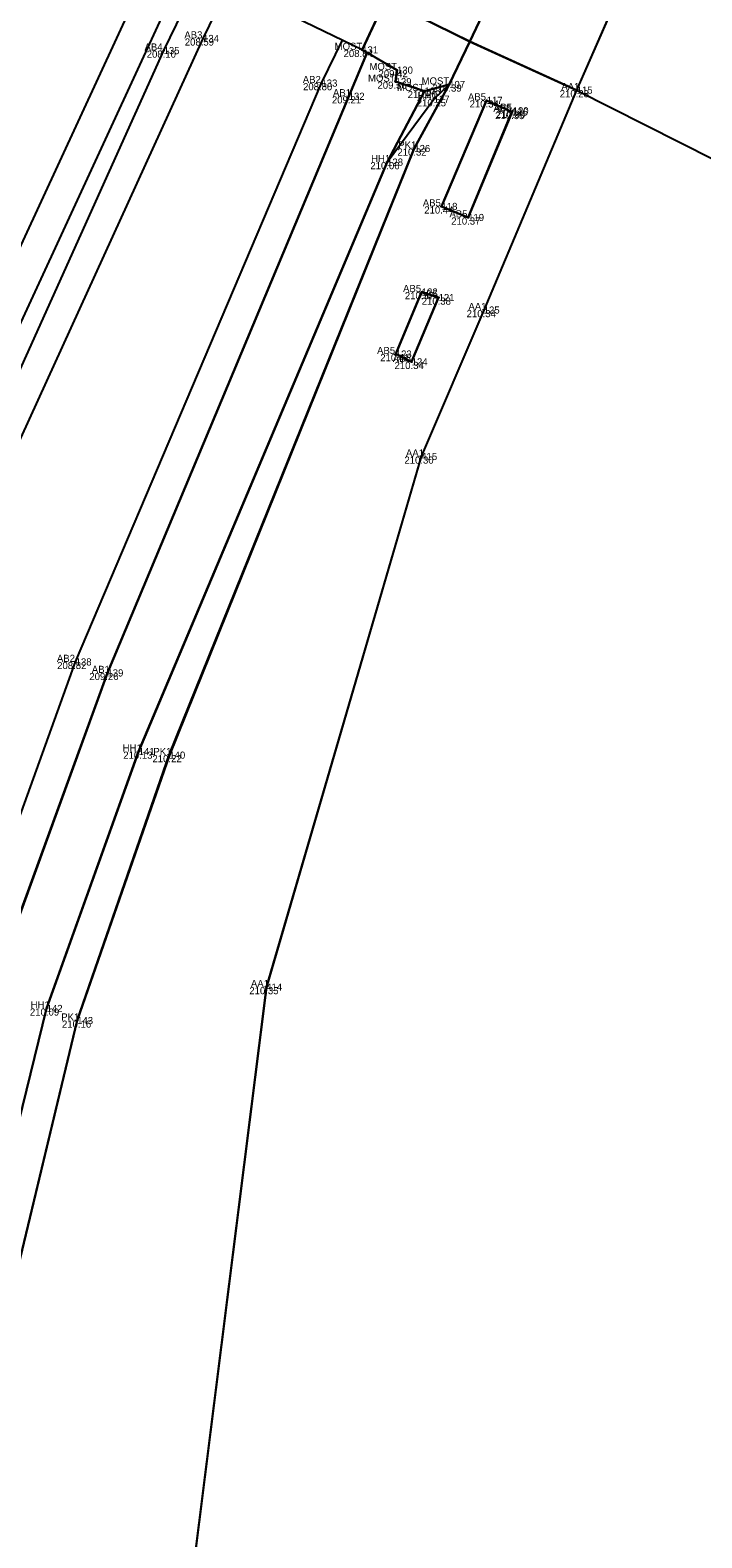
# Model space of a CAD drawing. Extents: x -263091 to -262565, y -1238731 to -1237092.
# Drawn here: x -262793.24 to -262774.42, y -1237721.96 to -1237679.73 of the extents above; entities that cross this region are included whole.
import ezdxf

# ---------------------------------------------------------------- set-up
doc = ezdxf.new("R2010")
doc.units = 0
for name, color, linetype in [('01_Hrana_betónu', 7, 'Continuous'), ('02_Oplotenie', 7, 'Continuous'), ('03_Asfalt', 7, 'Continuous'), ('04_Most', 7, 'Continuous'), ('05_Hrana_terénu', 7, 'Continuous'), ('08_Mimo_zelene', 7, 'Continuous'), ('10', 7, 'Continuous'), ('Groma (21)', 7, 'Continuous'), ('Groma (22)', 7, 'Continuous'), ('Groma (23)', 7, 'Continuous'), ('Groma (24)', 7, 'Continuous'), ('U004_Betónové_panely', 7, 'Continuous'), ('U004_Ostatné_plochy', 7, 'Continuous'), ('U004_Zeleň_mimo', 7, 'Continuous'), ('U004_Zeleň_vnútro', 7, 'Continuous'), ('U004_Zeleň_zatrávňovač', 7, 'Continuous'), ('U005_Ostatné_plochy', 7, 'Continuous'), ('U005_Zeleň_mimo', 7, 'Continuous')]:
    doc.layers.add(name, color=color, linetype=linetype)

msp = doc.modelspace()

# ---------------------------------------------------------------- linework, layer by layer
at = {"layer": '01_Hrana_betónu'}
msp.add_line((-262783.935, -1237680.285), (-262783.282, -1237678.876), dxfattribs=at)
for points in [[(-262828.366, -1237932.946), (-262828.106, -1237929.217), (-262827.649, -1237919.578), (-262827.369, -1237915.073), (-262826.968, -1237906.664), (-262825.835, -1237884.909), (-262824.318, -1237870.338), (-262822.252, -1237856.88), (-262820.394, -1237847.242), (-262816.344, -1237828.005), (-262811.527, -1237806.128), (-262807.485, -1237786.652), (-262805.817, -1237767.526), (-262804.904, -1237743.876), (-262804.544, -1237721.54), (-262802.773, -1237710.111), (-262800.948, -1237703.699), (-262796.578, -1237692.416), (-262790.297, -1237678.834), (-262789.671, -1237677.512)], [(-262788.862, -1237677.903), (-262789.612, -1237679.5), (-262795.758, -1237692.783), (-262800.102, -1237704.105), (-262801.904, -1237710.319), (-262803.638, -1237721.631), (-262804.041, -1237743.855), (-262804.886, -1237767.666), (-262806.567, -1237786.84), (-262810.653, -1237806.707), (-262815.575, -1237828.361), (-262819.614, -1237847.41), (-262821.404, -1237856.927), (-262823.638, -1237870.532), (-262825.083, -1237884.947), (-262826.299, -1237906.725), (-262827.242, -1237929.453), (-262827.527, -1237933.008)], [(-262788.441, -1237678.106), (-262789.499, -1237680.304), (-262796.488, -1237695.789), (-262799.561, -1237704.378), (-262801.599, -1237711.648), (-262803.17, -1237722.277), (-262803.523, -1237744.912), (-262804.331, -1237767.555), (-262806.033, -1237786.907), (-262810.428, -1237808.027), (-262815.321, -1237829.941), (-262818.5, -1237845.545), (-262820.865, -1237857.635), (-262822.962, -1237871.266), (-262824.386, -1237885.795), (-262825.49, -1237906.658), (-262826.835, -1237930.337), (-262826.931, -1237933.053)], [(-262825.987, -1237933.123), (-262825.899, -1237930.36), (-262825.137, -1237919.703), (-262824.89, -1237915.193), (-262824.65, -1237906.715), (-262823.596, -1237885.855), (-262822.137, -1237871.403), (-262820.061, -1237857.781), (-262817.692, -1237845.812), (-262814.459, -1237830.149), (-262809.645, -1237808.205), (-262805.191, -1237787.117), (-262803.484, -1237767.641), (-262802.568, -1237744.998), (-262802.266, -1237722.317), (-262800.862, -1237712.121), (-262798.805, -1237704.616), (-262795.791, -1237696.17), (-262788.393, -1237679.964), (-262787.674, -1237678.477)], [(-262785.076, -1237681.215), (-262784.491, -1237680.016)], [(-262783.803, -1237680.361), (-262791.072, -1237697.733), (-262794.156, -1237706.196), (-262796.111, -1237713.494), (-262797.353, -1237722.795), (-262798.006, -1237745.028), (-262798.995, -1237767.834), (-262800.837, -1237788.066), (-262805.174, -1237808.895), (-262810.048, -1237831.05), (-262813.207, -1237846.368), (-262815.438, -1237858.025), (-262817.519, -1237871.503), (-262819.01, -1237885.889), (-262819.761, -1237906.843), (-262819.991, -1237915.564)], [(-262820.488, -1237916.085), (-262820.893, -1237915.574), (-262820.599, -1237906.725), (-262819.894, -1237885.916), (-262818.364, -1237871.361), (-262816.365, -1237858.042), (-262814.122, -1237846.343), (-262810.891, -1237830.85), (-262806.137, -1237808.69), (-262801.736, -1237787.923), (-262799.952, -1237767.772), (-262798.979, -1237744.912), (-262798.159, -1237722.635), (-262796.927, -1237713.21), (-262795.035, -1237705.927), (-262791.963, -1237697.425), (-262785.076, -1237681.215)]]:
    msp.add_lwpolyline(points, dxfattribs=at)
at = {"layer": '02_Oplotenie'}
msp.add_lwpolyline([(-262782.476, -1237683.046), (-262789.338, -1237700.035), (-262791.92, -1237707.468), (-262793.68, -1237714.792), (-262794.853, -1237723.195), (-262795.698, -1237745.299), (-262796.564, -1237768.081), (-262798.719, -1237788.188), (-262802.852, -1237809.448), (-262807.527, -1237831.589), (-262810.764, -1237846.834), (-262812.842, -1237857.763), (-262814.888, -1237871.127), (-262816.319, -1237886.182), (-262816.945, -1237895.233), (-262817.687, -1237906.993), (-262818.366, -1237915.571), (-262818.764, -1237925.136)], dxfattribs=at)
at = {"layer": '03_Asfalt'}
for points in [[(-262724.746, -1237307.401), (-262727.828, -1237308.991), (-262728.093, -1237318.612), (-262728.491, -1237332.383), (-262729.117, -1237356.253), (-262729.803, -1237378.892), (-262730.272, -1237401.612), (-262730.633, -1237425.617), (-262730.625, -1237458.196), (-262731.018, -1237478.61), (-262730.917, -1237502.542), (-262731.001, -1237524.284), (-262731.468, -1237547.904), (-262731.892, -1237556.788), (-262732.535, -1237567.203), (-262733.679, -1237576.214), (-262736.504, -1237586.306), (-262740.104, -1237594.868), (-262744.783, -1237605.686), (-262753.189, -1237625.134), (-262761.527, -1237644.232), (-262769.984, -1237663.306), (-262774.379, -1237673.302), (-262777.928, -1237681.411)], [(-262777.928, -1237681.411), (-262780.531, -1237687.57), (-262782.281, -1237691.672), (-262786.624, -1237706.531), (-262791.645, -1237746.487), (-262793.969, -1237766.446), (-262796.149, -1237782.824), (-262801.035, -1237810.714), (-262803.747, -1237825.804), (-262807.32, -1237845.566), (-262809.566, -1237858.112), (-262812.403, -1237873.547), (-262813.944, -1237886.41), (-262814.5, -1237895.481), (-262816.945, -1237895.233)]]:
    msp.add_lwpolyline(points, dxfattribs=at)
at = {"layer": '04_Most'}
for points in [[(-262794.832, -1237673.105), (-262794.423, -1237672.239), (-262794.016, -1237671.765), (-262792.919, -1237672.236), (-262791.945, -1237673.175), (-262782.754, -1237677.736), (-262781.704, -1237678.283), (-262781.563, -1237678.037), (-262780.7, -1237678.426), (-262780.481, -1237679.127), (-262780.925, -1237680.054)], [(-262780.925, -1237680.054), (-262781.499, -1237681.254), (-262782.189, -1237681.436), (-262783, -1237681.174), (-262782.961, -1237680.851), (-262783.935, -1237680.285), (-262793.299, -1237675.758), (-262794.227, -1237675.288), (-262794.619, -1237675.515), (-262795.493, -1237674.504), (-262794.832, -1237673.105)]]:
    msp.add_lwpolyline(points, dxfattribs=at)
at = {"layer": '05_Hrana_terénu'}
msp.add_lwpolyline([(-262819.123, -1237925.833), (-262819.193, -1237924.361), (-262818.874, -1237915.472), (-262818.289, -1237906.84), (-262817.033, -1237886.241), (-262815.506, -1237871.209), (-262813.693, -1237857.604), (-262811.493, -1237846.649), (-262808.389, -1237831.401), (-262803.328, -1237809.401), (-262799.108, -1237788.219), (-262797.264, -1237767.972), (-262796.32, -1237745.233), (-262795.609, -1237723.113), (-262794.587, -1237714.488), (-262792.775, -1237707.13), (-262790.198, -1237699.936), (-262783.238, -1237683.427), (-262781.933, -1237681.667), (-262781.499, -1237681.254)], dxfattribs=at)
at = {"layer": '08_Mimo_zelene'}
for points in [[(-262781.713, -1237684.669), (-262780.448, -1237681.698), (-262779.738, -1237682.023), (-262780.967, -1237684.978)], [(-262782.55, -1237689.021), (-262782.994, -1237688.803), (-262782.266, -1237687.066), (-262781.795, -1237687.221)]]:
    msp.add_lwpolyline(points, close=True, dxfattribs=at)
at = {"layer": '10'}
msp.add_lwpolyline([(-262813.033, -1237664.011), (-262780.925, -1237680.054), (-262777.93, -1237681.41), (-262750.961, -1237695.025)], dxfattribs=at)
at = {"layer": 'Groma (21)'}
for centre in [(-262788.393, -1237679.964), (-262783.935, -1237680.285), (-262789.499, -1237680.304), (-262782.961, -1237680.851), (-262785.076, -1237681.215), (-262783, -1237681.174), (-262782.189, -1237681.436), (-262781.499, -1237681.254), (-262777.928, -1237681.412), (-262784.315, -1237681.584), (-262781.933, -1237681.667), (-262780.448, -1237681.698), (-262779.738, -1237682.023), (-262779.72, -1237681.99), (-262782.476, -1237683.046), (-262783.238, -1237683.427), (-262781.713, -1237684.669), (-262780.967, -1237684.978), (-262782.266, -1237687.066), (-262781.795, -1237687.221), (-262780.531, -1237687.57), (-262782.994, -1237688.803), (-262782.55, -1237689.021), (-262782.281, -1237691.672), (-262791.963, -1237697.425), (-262791.072, -1237697.733), (-262790.198, -1237699.936), (-262789.338, -1237700.035), (-262786.624, -1237706.531), (-262792.775, -1237707.13), (-262791.92, -1237707.468)]:
    msp.add_circle(centre, 0.01, dxfattribs=at)
at = {"layer": 'U004_Betónové_panely'}
msp.add_lwpolyline([(-262809.47, -1237744.21), (-262809.35, -1237719.32), (-262807.76, -1237709.13), (-262805.58, -1237701.26), (-262801.1, -1237689.83), (-262795.06, -1237676.27), (-262794.18, -1237676.61), (-262793.3, -1237675.76), (-262792.52, -1237674.26), (-262788.97, -1237676.03), (-262788.17, -1237676.43), (-262787.74, -1237676.65), (-262786.97, -1237677.03), (-262783.28, -1237678.88), (-262783.94, -1237680.28), (-262783.8, -1237680.36), (-262791.07, -1237697.73), (-262794.16, -1237706.2), (-262796.11, -1237713.49), (-262797.35, -1237722.8)], dxfattribs=at)
msp.add_lwpolyline([(-262809.47, -1237744.21), (-262809.35, -1237719.32), (-262807.76, -1237709.13), (-262805.58, -1237701.26), (-262801.1, -1237689.83), (-262795.06, -1237676.27), (-262794.18, -1237676.61), (-262793.3, -1237675.76), (-262792.52, -1237674.26), (-262788.97, -1237676.03), (-262788.17, -1237676.43), (-262787.74, -1237676.65), (-262786.97, -1237677.03), (-262783.28, -1237678.88), (-262783.94, -1237680.28), (-262783.8, -1237680.36), (-262791.07, -1237697.73), (-262794.16, -1237706.2), (-262796.11, -1237713.49), (-262797.35, -1237722.8)], dxfattribs=at)
at = {"layer": 'U004_Ostatné_plochy'}
for points in [[(-262783.94, -1237680.28), (-262783.28, -1237678.88), (-262780.92, -1237680.05), (-262781.5, -1237681.25), (-262782.19, -1237681.44), (-262783, -1237681.17), (-262782.96, -1237680.85)], [(-262781.71, -1237684.67), (-262780.45, -1237681.7), (-262779.74, -1237682.02), (-262780.97, -1237684.98)], [(-262781.8, -1237687.22), (-262782.55, -1237689.02), (-262782.99, -1237688.8), (-262782.27, -1237687.07)]]:
    msp.add_lwpolyline(points, close=True, dxfattribs=at)
msp.add_lwpolyline([(-262782.19, -1237681.44), (-262783, -1237681.17), (-262782.96, -1237680.85), (-262783.94, -1237680.28), (-262783.28, -1237678.88), (-262780.92, -1237680.05), (-262781.5, -1237681.25), (-262782.19, -1237681.44)], dxfattribs=at)
at = {"layer": 'U004_Zeleň_mimo'}
msp.add_lwpolyline([(-262794.85, -1237723.2), (-262793.68, -1237714.79), (-262791.92, -1237707.47), (-262789.34, -1237700.03), (-262782.48, -1237683.05), (-262781.5, -1237681.25), (-262780.92, -1237680.05), (-262777.93, -1237681.41), (-262780.53, -1237687.57), (-262782.28, -1237691.67), (-262786.62, -1237706.53), (-262791.65, -1237746.49)], dxfattribs=at)
for points in [[(-262780.97, -1237684.98), (-262779.74, -1237682.02), (-262780.45, -1237681.7), (-262781.71, -1237684.67)], [(-262781.8, -1237687.22), (-262782.27, -1237687.07), (-262782.99, -1237688.8), (-262782.55, -1237689.02)]]:
    msp.add_lwpolyline(points, close=True, dxfattribs=at)
at = {"layer": 'U004_Zeleň_vnútro'}
msp.add_lwpolyline([(-262795.61, -1237723.11), (-262794.59, -1237714.49), (-262792.78, -1237707.13), (-262790.2, -1237699.94), (-262783.24, -1237683.43), (-262782.19, -1237681.44), (-262781.5, -1237681.25), (-262782.48, -1237683.05), (-262789.34, -1237700.03), (-262791.92, -1237707.47), (-262793.68, -1237714.79), (-262794.85, -1237723.2)], dxfattribs=at)
msp.add_lwpolyline([(-262795.61, -1237723.11), (-262794.59, -1237714.49), (-262792.78, -1237707.13), (-262790.2, -1237699.94), (-262783.24, -1237683.43), (-262782.19, -1237681.44), (-262781.5, -1237681.25), (-262782.48, -1237683.05), (-262789.34, -1237700.03), (-262791.92, -1237707.47), (-262793.68, -1237714.79), (-262794.85, -1237723.2)], dxfattribs=at)
at = {"layer": 'U004_Zeleň_zatrávňovač'}
msp.add_lwpolyline([(-262797.35, -1237722.8), (-262796.11, -1237713.49), (-262794.16, -1237706.2), (-262791.07, -1237697.73), (-262783.8, -1237680.36), (-262782.96, -1237680.85), (-262783, -1237681.17), (-262782.19, -1237681.44), (-262783.24, -1237683.43), (-262790.2, -1237699.94), (-262792.78, -1237707.13), (-262794.59, -1237714.49), (-262795.61, -1237723.11)], dxfattribs=at)
msp.add_lwpolyline([(-262797.35, -1237722.8), (-262796.11, -1237713.49), (-262794.16, -1237706.2), (-262791.07, -1237697.73), (-262783.8, -1237680.36), (-262782.96, -1237680.85), (-262783, -1237681.17), (-262782.19, -1237681.44), (-262783.24, -1237683.43), (-262790.2, -1237699.94), (-262792.78, -1237707.13), (-262794.59, -1237714.49), (-262795.61, -1237723.11)], dxfattribs=at)
at = {"layer": 'U005_Ostatné_plochy'}
msp.add_lwpolyline([(-262783.28, -1237678.88), (-262782.75, -1237677.74), (-262781.56, -1237678.04), (-262780.7, -1237678.43), (-262780.48, -1237679.13), (-262780.92, -1237680.05)], close=True, dxfattribs=at)
msp.add_lwpolyline([(-262780.92, -1237680.05), (-262783.28, -1237678.88), (-262782.75, -1237677.74), (-262781.56, -1237678.04), (-262780.7, -1237678.43), (-262780.48, -1237679.13), (-262780.92, -1237680.05)], dxfattribs=at)
at = {"layer": 'U005_Zeleň_mimo'}
msp.add_lwpolyline([(-262744.78, -1237605.69), (-262753.19, -1237625.13), (-262761.53, -1237644.23), (-262769.98, -1237663.31), (-262774.38, -1237673.3), (-262777.93, -1237681.41), (-262780.92, -1237680.05), (-262780.48, -1237679.13), (-262780.18, -1237678.91), (-262778.14, -1237677.63), (-262776.66, -1237673.92), (-262776.48, -1237670.97), (-262772.02, -1237662.27), (-262762.9, -1237643.63), (-262753.7, -1237624.77), (-262745.09, -1237605.54)], dxfattribs=at)

# ---------------------------------------------------------------- texts
at = {"layer": 'Groma (22)'}
for s, p in [('134', (-262788.393, -1237680.064)), ('135', (-262789.499, -1237680.404)), ('131', (-262783.935, -1237680.385)), ('133', (-262785.076, -1237681.315)), ('129', (-262783, -1237681.274)), ('130', (-262782.961, -1237680.951)), ('132', (-262784.315, -1237681.684)), ('108', (-262782.189, -1237681.536)), ('107', (-262781.499, -1237681.354)), ('115', (-262777.928, -1237681.512)), ('127', (-262781.933, -1237681.767)), ('117', (-262780.448, -1237681.798)), ('116', (-262779.738, -1237682.123)), ('120', (-262779.72, -1237682.09)), ('126', (-262782.476, -1237683.146)), ('128', (-262783.238, -1237683.527)), ('118', (-262781.713, -1237684.769)), ('119', (-262780.967, -1237685.078)), ('122', (-262782.266, -1237687.166)), ('121', (-262781.795, -1237687.321)), ('125', (-262780.531, -1237687.67)), ('123', (-262782.994, -1237688.903)), ('124', (-262782.55, -1237689.121)), ('415', (-262782.281, -1237691.772)), ('138', (-262791.963, -1237697.525)), ('139', (-262791.072, -1237697.833)), ('141', (-262790.198, -1237700.036)), ('140', (-262789.338, -1237700.135)), ('414', (-262786.624, -1237706.631)), ('142', (-262792.775, -1237707.23)), ('143', (-262791.92, -1237707.568))]:
    msp.add_text(s, height=0.2, dxfattribs=at).set_placement(p)
at = {"layer": 'Groma (23)'}
for s, p in [('208.59', (-262788.905, -1237680.164)), ('208.84', (-262784.456, -1237680.485)), ('208.10', (-262789.971, -1237680.504)), ('209.42', (-262783.478, -1237681.051)), ('208.80', (-262785.592, -1237681.415)), ('209.36', (-262783.507, -1237681.374)), ('210.20', (-262782.661, -1237681.636)), ('210.39', (-262781.967, -1237681.454)), ('210.28', (-262778.401, -1237681.612)), ('209.21', (-262784.783, -1237681.784)), ('210.25', (-262782.406, -1237681.867)), ('210.34', (-262780.926, -1237681.898)), ('210.35', (-262780.211, -1237682.223)), ('210.36', (-262780.188, -1237682.19)), ('210.32', (-262782.949, -1237683.246)), ('210.06', (-262783.706, -1237683.627)), ('210.44', (-262782.196, -1237684.869)), ('210.37', (-262781.441, -1237685.178)), ('210.37', (-262782.74, -1237687.266)), ('210.38', (-262782.268, -1237687.421)), ('210.34', (-262781.009, -1237687.77)), ('210.41', (-262783.429, -1237689.003)), ('210.34', (-262783.028, -1237689.221)), ('210.30', (-262782.753, -1237691.872)), ('208.82', (-262792.48, -1237697.625)), ('209.26', (-262791.579, -1237697.933)), ('210.13', (-262790.628, -1237700.136)), ('210.22', (-262789.811, -1237700.235)), ('210.35', (-262787.097, -1237706.731)), ('210.09', (-262793.243, -1237707.33)), ('210.16', (-262792.345, -1237707.668))]:
    msp.add_text(s, height=0.2, dxfattribs=at).set_placement(p)
at = {"layer": 'Groma (24)'}
for s, p in [('AB3', (-262788.917, -1237679.964)), ('AB4', (-262790.033, -1237680.304)), ('MOST', (-262784.707, -1237680.285)), ('MOST', (-262783.733, -1237680.851)), ('AB2', (-262785.6, -1237681.215)), ('MOST', (-262783.772, -1237681.174)), ('MOST', (-262782.271, -1237681.254)), ('AB1', (-262784.753, -1237681.584)), ('MOST', (-262782.961, -1237681.436)), ('HH1', (-262782.38, -1237681.667)), ('AB5', (-262780.972, -1237681.698)), ('AA1', (-262778.356, -1237681.412)), ('AB5', (-262780.262, -1237682.023)), ('AB5', (-262780.244, -1237681.99)), ('HH1', (-262783.685, -1237683.427)), ('PK1', (-262782.923, -1237683.046)), ('AB5', (-262782.237, -1237684.669)), ('AB5', (-262781.491, -1237684.978)), ('AB5', (-262782.79, -1237687.066)), ('AB5', (-262782.319, -1237687.221)), ('AA1', (-262780.959, -1237687.57)), ('AB5', (-262783.518, -1237688.803)), ('AB5', (-262783.074, -1237689.021)), ('AA1', (-262782.709, -1237691.672)), ('AB2', (-262792.487, -1237697.425)), ('AB1', (-262791.51, -1237697.733)), ('HH1', (-262790.645, -1237699.936)), ('PK1', (-262789.785, -1237700.035)), ('AA1', (-262787.052, -1237706.531)), ('HH1', (-262793.222, -1237707.13)), ('PK1', (-262792.367, -1237707.468))]:
    msp.add_text(s, height=0.2, dxfattribs=at).set_placement(p)

doc.saveas('drawing.dxf')
